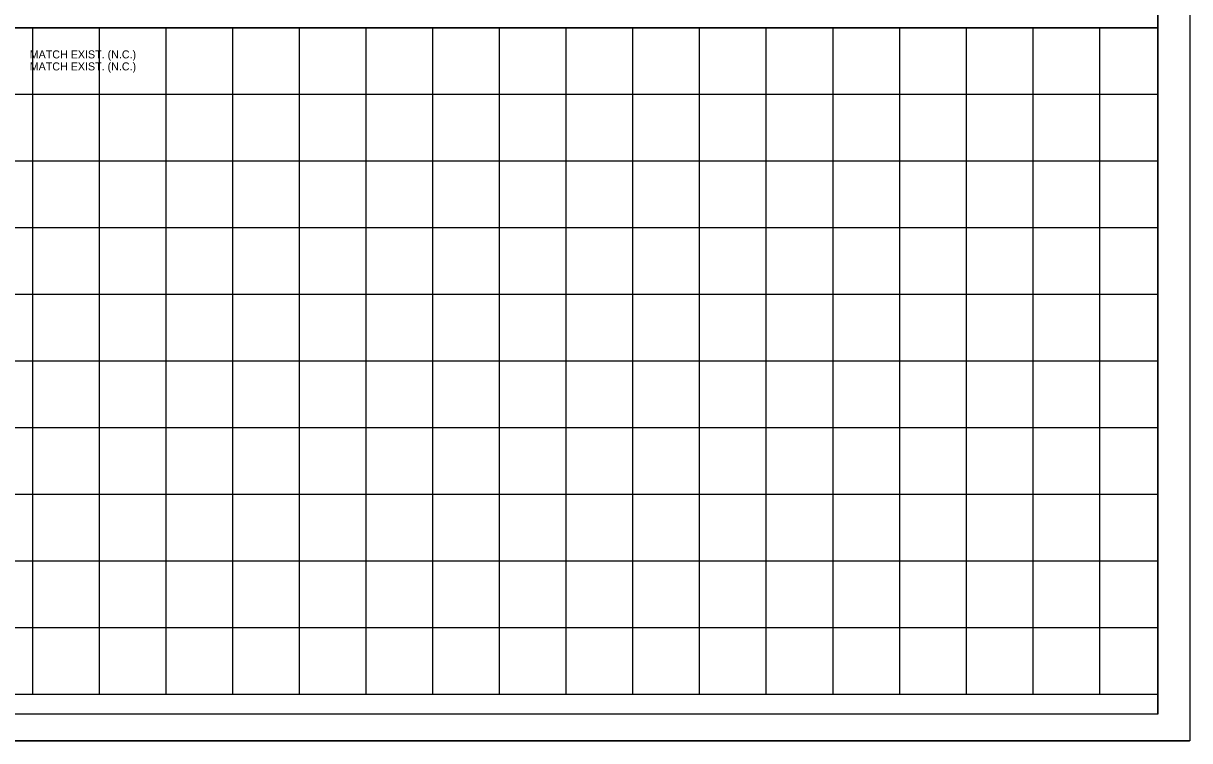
# Model space of a CAD drawing. Extents: x 816090 to 819714, y 1801340 to 1803641.
# Drawn here: x 816882 to 817757, y 1801340 to 1801878 of the extents above; entities that cross this region are included whole.
import ezdxf

# ---------------------------------------------------------------- set-up
doc = ezdxf.new("R2010")
doc.units = 0
for name, color, linetype in [('R_Border', 7, 'Continuous'), ('R_Horz Alg Annot', 7, 'Continuous'), ('R_No Plot', 7, 'Continuous')]:
    doc.layers.add(name, color=color, linetype=linetype)

msp = doc.modelspace()

# ---------------------------------------------------------------- linework, layer by layer
at = {"layer": 'R_Border'}
for p, q in [((817732.96, 1801359.83), (817732.96, 1802387.13)), ((817732.96, 1801874.53), (816152.06, 1801874.53)), ((816889.36, 1801374.53), (816889.36, 1801874.53)), ((816939.36, 1801374.53), (816939.36, 1801874.53)), ((816989.36, 1801374.53), (816989.36, 1801874.53)), ((817039.36, 1801374.53), (817039.36, 1801874.53)), ((817089.36, 1801374.53), (817089.36, 1801874.53)), ((817139.36, 1801374.53), (817139.36, 1801874.53)), ((817189.36, 1801374.53), (817189.36, 1801874.53)), ((817239.36, 1801374.53), (817239.36, 1801874.53)), ((817289.36, 1801374.53), (817289.36, 1801874.53)), ((817339.36, 1801374.53), (817339.36, 1801874.53)), ((817389.36, 1801374.53), (817389.36, 1801874.53)), ((817439.36, 1801374.53), (817439.36, 1801874.53)), ((817489.36, 1801374.53), (817489.36, 1801874.53)), ((817539.36, 1801374.53), (817539.36, 1801874.53)), ((817589.36, 1801374.53), (817589.36, 1801874.53)), ((817639.36, 1801374.53), (817639.36, 1801874.53)), ((817689.36, 1801374.53), (817689.36, 1801874.53)), ((817732.96, 1801824.53), (816152.06, 1801824.53)), ((817732.96, 1801774.53), (816152.06, 1801774.53)), ((817732.96, 1801724.53), (816152.06, 1801724.53)), ((817732.96, 1801674.53), (816152.06, 1801674.53)), ((817732.96, 1801624.53), (816152.06, 1801624.53)), ((817732.96, 1801574.53), (816152.06, 1801574.53)), ((817732.96, 1801524.53), (816152.06, 1801524.53)), ((817732.96, 1801474.53), (816152.06, 1801474.53)), ((817732.96, 1801424.53), (816152.06, 1801424.53)), ((817732.96, 1801374.53), (816152.06, 1801374.53)), ((817732.96, 1801359.83), (816152.06, 1801359.83))]:
    msp.add_line(p, q, dxfattribs=at)
at = {"layer": 'R_No Plot'}
msp.add_line((816090.06, 1801339.93), (817756.73, 1801339.93), dxfattribs=at)
for points in [[(816090.06, 1802406.62), (817756.76, 1802406.62), (817756.76, 1801339.93), (816090.06, 1801339.93)], [(817419.76, 1802387.13), (817419.76, 1802337.73), (817500.32, 1802337.73), (817618.87, 1802337.73), (817618.87, 1802227.73), (817732.96, 1802227.73), (817732.96, 1801874.53), (816152.06, 1801874.53), (816152.06, 1802387.13)], [(816152.06, 1801874.53), (817732.96, 1801874.53), (817732.96, 1801359.83), (816152.06, 1801359.83)], [(816152.06, 1801874.53), (817732.96, 1801874.53), (817732.96, 1801359.83), (816152.06, 1801359.83)]]:
    msp.add_lwpolyline(points, close=True, dxfattribs=at)

# ---------------------------------------------------------------- texts
at = {"layer": 'R_Horz Alg Annot'}
for p in [(816887.08, 1801851.51), (816887.08, 1801842.51)]:
    msp.add_text('MATCH EXIST. (N.C.)', height=6, dxfattribs=at).set_placement(p)

doc.saveas('drawing.dxf')
